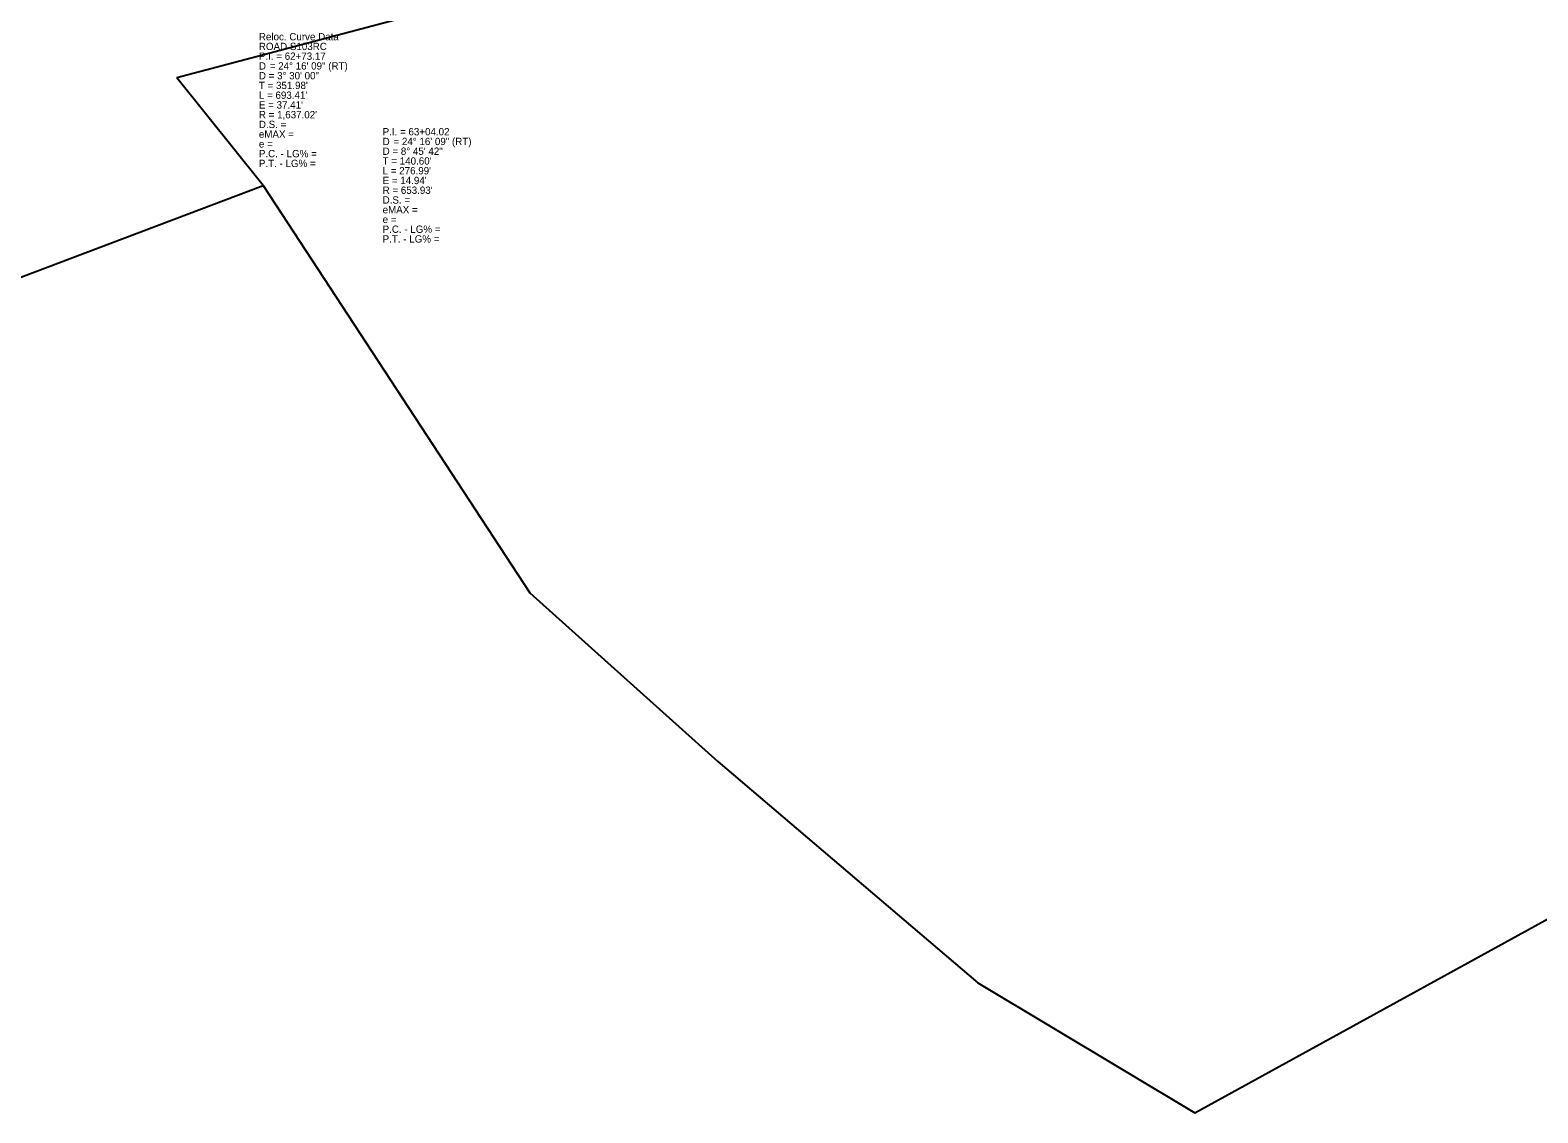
# Model space of a CAD drawing. Extents: x 1964982 to 1970527, y 1116335 to 1119906.
# Drawn here: x 1967748 to 1969294, y 1116335 to 1117446 of the extents above; entities that cross this region are included whole.
import ezdxf

# ---------------------------------------------------------------- set-up
doc = ezdxf.new("R2010")
doc.units = 0
doc.layers.add('RD_EX_DV_Prop', color=7, linetype='Continuous')
doc.layers.add('RD_HC_txCode', color=7, linetype='Continuous')

msp = doc.modelspace()

# ---------------------------------------------------------------- linework, layer by layer
at = {"layer": 'RD_EX_DV_Prop'}
for p, q in [((1968204.3, 1117478.1), (1967898.1, 1117396.7)), ((1967986.4, 1117286.2), (1967898.1, 1117396.7)), ((1967582.6, 1117133.3), (1967986.4, 1117286.2)), ((1967986.4, 1117286.2), (1968260.1, 1116868.2)), ((1968260.1, 1116868.2), (1968452.8, 1116695.3)), ((1968941.8, 1116334.8), (1969776.6, 1116794.1)), ((1968452.8, 1116695.3), (1968719.5, 1116468.1)), ((1968719.5, 1116468.1), (1968941.8, 1116334.8))]:
    msp.add_line(p, q, dxfattribs=at)

# ---------------------------------------------------------------- texts
at = {"layer": 'RD_HC_txCode'}
for s, p in [('Reloc. Curve Data', (1967982.1, 1117435.1)), ('ROAD S103RC', (1967982.1, 1117425.1)), ('P.I. = 62+73.17', (1967982.1, 1117415.1)), ('D', (1967982.1, 1117405.1)), ('D = 3%%d 30\' 00"', (1967982.1, 1117395.1)), ('    = 24%%d 16\' 09" (RT)', (1967982.1, 1117405.1)), ("T = 351.98'", (1967982.1, 1117385.1)), ("L = 693.41'", (1967982.1, 1117375.1)), ("E = 37.41'", (1967982.1, 1117365.1)), ("R = 1,637.02'", (1967982.1, 1117355.1)), ('D.S. =', (1967982.1, 1117345.1)), ('eMAX = ', (1967982.1, 1117335.1)), ('P.I. = 63+04.02', (1968109, 1117337.6)), ('e = ', (1967982.1, 1117325.1)), ('P.C. - LG% = ', (1967982.1, 1117315.1)), ('D', (1968109, 1117327.6)), ('D = 8%%d 45\' 42"', (1968109, 1117317.6)), ('    = 24%%d 16\' 09" (RT)', (1968109, 1117327.6)), ('P.T. - LG% = ', (1967982.1, 1117305.1)), ("T = 140.60'", (1968109, 1117307.6)), ("L = 276.99'", (1968109, 1117297.6)), ("E = 14.94'", (1968109, 1117287.6)), ("R = 653.93'", (1968109, 1117277.6)), ('D.S. = ', (1968109, 1117267.6)), ('eMAX = ', (1968109, 1117257.6)), ('e = ', (1968109, 1117247.6)), ('P.C. - LG% = ', (1968109, 1117237.6)), ('P.T. - LG% = ', (1968109, 1117227.6))]:
    msp.add_text(s, height=7.5, dxfattribs=at).set_placement(p)

doc.saveas('drawing.dxf')
